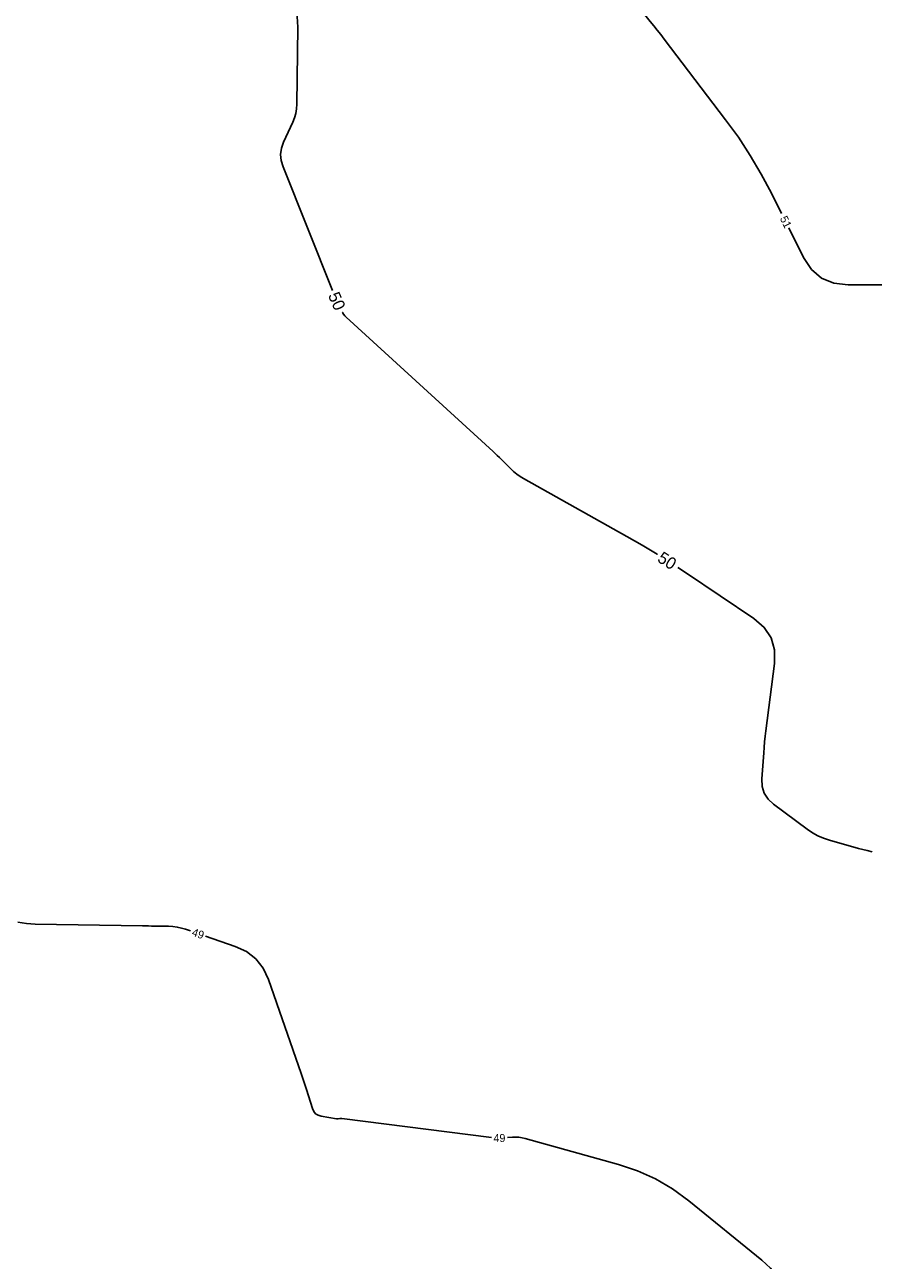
# Model space of a CAD drawing. Extents: x 2384780 to 2405861, y 547869 to 573706.
# Drawn here: x 2392801.8 to 2393014, y 553123.7 to 553432.4 of the extents above; entities that cross this region are included whole.
import ezdxf

# ---------------------------------------------------------------- set-up
doc = ezdxf.new("R2010")
doc.units = 0
doc.layers.add('Old_Level_60', color=7, linetype='Continuous')
doc.layers.add('Old_Level_61', color=7, linetype='Continuous')

msp = doc.modelspace()

# ---------------------------------------------------------------- linework, layer by layer
at = {"layer": 'Old_Level_60'}
for points in [[(2392949.96225, 553472.56475), (2392949.6145, 553453.712), (2392949.646, 553452.08725), (2392949.80025, 553450.47875), (2392950.0775, 553448.887), (2392950.47775, 553447.312), (2392951.98625, 553442.1935), (2392952.35975, 553441.1235), (2392952.83375, 553440.1065), (2392953.4085, 553439.143), (2392954.084, 553438.23275), (2392958.22525, 553433.19), (2392959.10775, 553432.1055), (2392959.98025, 553431.013), (2392960.84275, 553429.91275), (2392961.6955, 553428.80475), (2392977.06875, 553408.6415), (2392980.25525, 553404.25375), (2392983.227, 553399.73175), (2392985.98375, 553395.0755), (2392988.5255, 553390.285), (2392991.06775, 553385.21225)], [(2392992.86, 553381.63625), (2392996.55775, 553374.2575), (2392998.544, 553371.25225), (2393001.06025, 553369.10575), (2393004.10675, 553367.81775), (2393007.68325, 553367.3885), (2393030.38675, 553367.3885)], [(2392843.2915, 553205.96825), (2392842.05, 553206.396), (2392841.0175, 553206.70725), (2392839.9705, 553206.935), (2392838.90875, 553207.079), (2392837.832, 553207.1395), (2392834.29125, 553207.20025), (2392833.5325, 553207.21325), (2392832.77375, 553207.22625), (2392832.015, 553207.23925), (2392831.25625, 553207.25225), (2392804.47125, 553207.712), (2392802.2585, 553207.85625), (2392800.09125, 553208.212)], [(2392918.517, 553154.37025), (2392881.13675, 553159.093), (2392881.00525, 553159.105), (2392880.874, 553159.10825), (2392880.74275, 553159.10275), (2392880.61175, 553159.088), (2392880.1835, 553159.026), (2392880.09175, 553159.01625), (2392880.00025, 553159.014), (2392879.90875, 553159.019), (2392879.81725, 553159.03125), (2392875.93725, 553159.70925), (2392875.178, 553159.93725), (2392874.56325, 553160.33), (2392874.09325, 553160.88775), (2392873.76775, 553161.6105), (2392872.28325, 553166.33025), (2392871.96125, 553167.34025), (2392871.6315, 553168.34775), (2392871.29425, 553169.35275), (2392870.949, 553170.35525), (2392862.76625, 553193.824), (2392861.43775, 553196.65925), (2392859.6055, 553198.98875), (2392857.26925, 553200.8125), (2392854.429, 553202.13075), (2392847.07325, 553204.66525)], [(2392998.28125, 553099.09875), (2392997.21275, 553101.38675), (2392992.66025, 553114.416), (2392991.51975, 553117.09225), (2392990.04925, 553119.53675), (2392988.249, 553121.7495), (2392986.119, 553123.731), (2392967.83575, 553138.592), (2392963.7995, 553141.54775), (2392959.527, 553144.0455), (2392955.01775, 553146.0855), (2392950.27175, 553147.66775), (2392926.9865, 553154.1465), (2392926.19825, 553154.33), (2392925.403, 553154.444), (2392924.60075, 553154.48825), (2392923.79175, 553154.463), (2392922.50625, 553154.368)]]:
    msp.add_lwpolyline(points, dxfattribs=at)
at = {"layer": 'Old_Level_61'}
for points in [[(2392878.8145, 553366.0055), (2392866.415, 553396.886), (2392865.95575, 553398.439), (2392865.82775, 553399.98375), (2392866.0315, 553401.52025), (2392866.5665, 553403.04875), (2392868.856, 553408.0285), (2392869.28725, 553409.109), (2392869.59975, 553410.21625), (2392869.7935, 553411.3505), (2392869.8685, 553412.5115), (2392870.1245, 553431.7535), (2392869.89475, 553435.79575), (2392869.09675, 553439.676), (2392867.72975, 553443.394), (2392865.794, 553446.95025), (2392857.71275, 553459.6005)], [(2392960.0215, 553300.01525), (2392959.90925, 553300.08575), (2392956.17525, 553302.3295), (2392952.39575, 553304.49925), (2392926.5265, 553319.0105), (2392925.6655, 553319.533), (2392924.8465, 553320.1105), (2392924.06925, 553320.74325), (2392923.334, 553321.43125), (2392921.00025, 553323.76875), (2392920.49725, 553324.26675), (2392919.98875, 553324.759), (2392919.47475, 553325.24525), (2392918.95525, 553325.72575), (2392882.20925, 553359.315), (2392881.854, 553359.672), (2392881.53775, 553360.05775), (2392881.26025, 553360.4725), (2392881.235, 553360.5195)], [(2393013.6545, 553225.785), (2393012.44275, 553226.0405), (2393010.23925, 553226.609), (2393003.07175, 553228.62875), (2393001.56775, 553229.1265), (2393000.1275, 553229.754), (2392998.75125, 553230.511), (2392997.4385, 553231.398), (2392989.05725, 553237.6275), (2392987.67775, 553238.9135), (2392986.7315, 553240.39875), (2392986.218, 553242.08375), (2392986.13775, 553243.96775), (2392986.583, 553250.44875), (2392986.68825, 553251.8365), (2392986.8135, 553253.22225), (2392986.95875, 553254.60625), (2392987.12375, 553255.98825), (2392989.25425, 553272.7965), (2392989.27675, 553276.20075), (2392988.43125, 553279.21025), (2392986.718, 553281.825), (2392984.13675, 553284.04475), (2392967.241, 553295.37675), (2392965.08275, 553296.7935)]]:
    msp.add_lwpolyline(points, dxfattribs=at)

# ---------------------------------------------------------------- texts
at = {"layer": 'Old_Level_60'}
for s, rotation, p in [('51', 296.6172806, (2392990.562, 553383.98975)), ('49', 340.9883806, (2392843.45725, 553204.8535)), ('49', 359.9697278, (2392919.02975, 553153.23975))]:
    msp.add_text(s, height=2, rotation=rotation, dxfattribs=at).set_placement(p)
at = {"layer": 'Old_Level_61'}
for rotation, p in [(293.8067694, (2392877.61325, 553364.78)), (327.5218333, (2392959.76375, 553298.42225))]:
    msp.add_text('50', height=3, rotation=rotation, dxfattribs=at).set_placement(p)

doc.saveas('drawing.dxf')
